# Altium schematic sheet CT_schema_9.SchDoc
size 278 x 170 mm
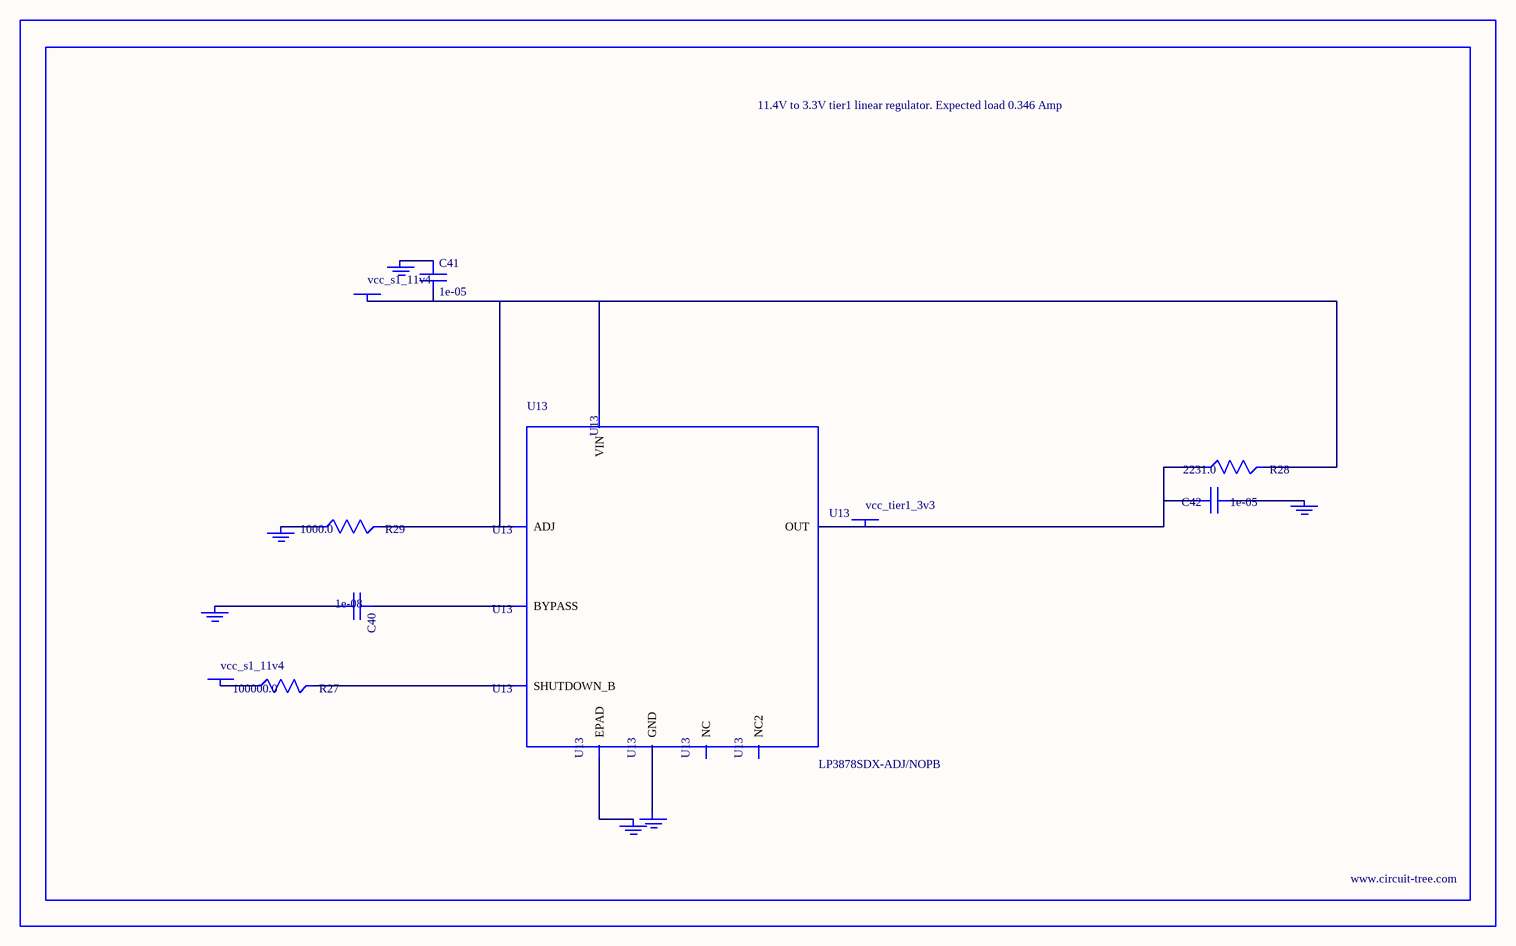
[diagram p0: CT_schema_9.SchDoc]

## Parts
BORDER8  (no value)
C40  1e-08  [C0402]
C41  1e-05  [C1210]
C42  1e-05  [C1210]
GND_INSTANCE_8_0  (no value)
GND_INSTANCE_8_1  (no value)
GND_INSTANCE_8_2  (no value)
GND_INSTANCE_8_3  (no value)
GND_INSTANCE_8_4  (no value)
GND_INSTANCE_8_5  (no value)
POWER_INSTANCE_8_0  vcc_s1_11v4
POWER_INSTANCE_8_1  vcc_s1_11v4
POWER_INSTANCE_8_2  vcc_tier1_3v3
R27  100000.0  [R0603]
R28  2231.0  [R0603]
R29  1000.0  [R0603]
U13  LP3878SDX-ADJ/NOPB  [WSON-8]

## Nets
NetC40_1: C40.1 U13.1(BYPASS)
NetC40_2: C40.2 GND_INSTANCE_8_0.0(GND)
NetC41_1: C41.1 GND_INSTANCE_8_1.0(GND)
NetC41_2: C41.2 POWER_INSTANCE_8_0.0(PWR) R28.2 R29.2 U13.4(VIN) U13.6(ADJ)
NetC42_1: C42.1 GND_INSTANCE_8_2.0(GND)
NetC42_2: C42.2 POWER_INSTANCE_8_2.0(PWR) R28.1 U13.5(OUT)
NetGND_INSTANCE_8_3_0: GND_INSTANCE_8_3.0(GND) R29.1
NetGND_INSTANCE_8_4_0: GND_INSTANCE_8_4.0(GND) U13.PAD(EPAD)
NetGND_INSTANCE_8_5_0: GND_INSTANCE_8_5.0(GND) U13.3(GND)
NetPOWER_INSTANCE_8_1_0: POWER_INSTANCE_8_1.0(PWR) R27.1
NetR27_2: R27.2 U13.8(SHUTDOWN_B)

Not connected (* = marked no-connect by the designer): U13 2(NC) 7(NC2)

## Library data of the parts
BORDER8 = BORDER_PAGE8
C40 = C0402C103K3RAC
C41 = C1210C106K5PACTU
C42 = GRM32DR61E106MA12L
GND_INSTANCE_8_0-GND_INSTANCE_8_5 = GND
POWER_INSTANCE_8_0-POWER_INSTANCE_8_2 = PWR
R27 = RC0603JR-07100KL
R28 = R28
R29 = RC0603JR-071KL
